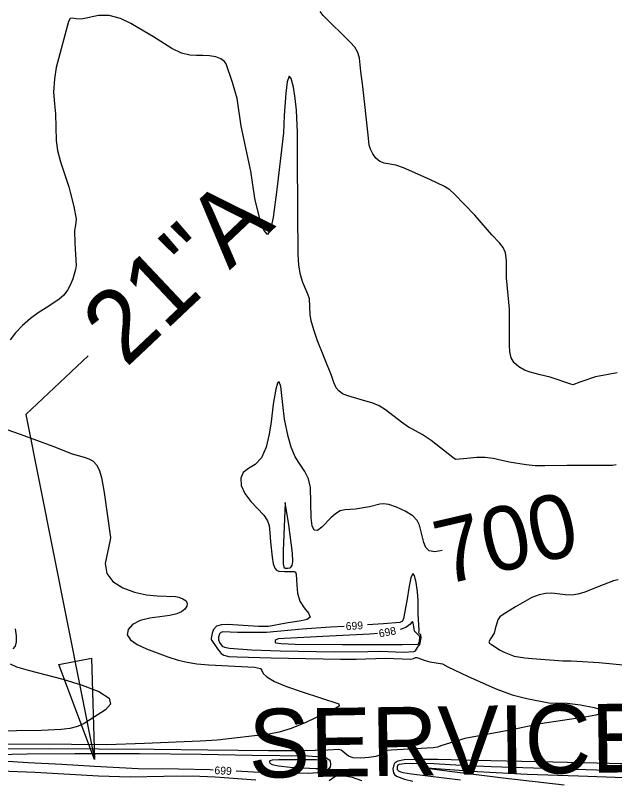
# Model space of a CAD drawing. Extents: x -291892836 to 2945206, y -477993085 to 1832792.
# Drawn here: x 1849872.3 to 1850181.6, y 543914.3 to 544308.6 of the extents above; entities that cross this region are included whole.
import ezdxf

# ---------------------------------------------------------------- set-up
doc = ezdxf.new("R2010")
doc.units = 0
for name, color, linetype in [('DT_X_Contour_Minor', 7, 'Continuous'), ('Level 19', 7, 'Continuous'), ('Level 40', 7, 'Continuous')]:
    doc.layers.add(name, color=color, linetype=linetype)

msp = doc.modelspace()

# ---------------------------------------------------------------- linework, layer by layer
at = {"layer": 'DT_X_Contour_Minor'}
for points in [[(1850180.45, 544076.42), (1850173.94, 544076.29), (1850156.91, 544076.39), (1850145.53, 544076.12), (1850140.58, 544076.25), (1850135.89, 544076.63), (1850127.25, 544078.09), (1850118.95, 544079.96), (1850114.75, 544080.5), (1850110.52, 544080.53), (1850103.63, 544079.8), (1850099.47, 544079.39), (1850098.13, 544080.44), (1850086.86, 544089.2), (1850082.36, 544092.38), (1850076.95, 544095.32), (1850075.23, 544096.11), (1850071.55, 544098.69), (1850063.34, 544105.07), (1850060.09, 544107.07), (1850056.87, 544108.56), (1850050.37, 544110.5), (1850043.86, 544112.24), (1850041.19, 544113.38), (1850039.23, 544114.81), (1850037.93, 544116.37), (1850036.72, 544119.12), (1850035.57, 544122.73), (1850028.23, 544140.77), (1850026.37, 544146.28), (1850025.04, 544150.97), (1850024.44, 544154.35), (1850024.09, 544162.41), (1850023.34, 544164.7), (1850020.68, 544170.73), (1850019.44, 544174.76), (1850018.68, 544179.64), (1850018.32, 544185.39), (1850018.13, 544206.85), (1850018.05, 544236.69), (1850018, 544248.15), (1850017.41, 544259.68), (1850016.77, 544265.63), (1850015.84, 544271.54), (1850014.75, 544275.99), (1850013.66, 544277.25), (1850012.71, 544274.23), (1850011.95, 544268.48), (1850011.17, 544256.94), (1850010.68, 544248.07), (1850007.22, 544218.69), (1850005.38, 544204.25), (1850004.08, 544198.13), (1850002.48, 544195.49), (1850000.63, 544197.72), (1849998.77, 544203.05), (1849996.19, 544213.29), (1849995.21, 544218.91), (1849993.84, 544228.19), (1849988.96, 544251.51), (1849986.88, 544265.7), (1849984.41, 544274), (1849981.22, 544283.63), (1849980.21, 544284.96), (1849978.45, 544286.19), (1849975.77, 544287.14), (1849972.5, 544287.75), (1849969.09, 544287.97), (1849965.82, 544287.86), (1849962.36, 544288), (1849958.18, 544289.11), (1849953.06, 544291.59), (1849943.63, 544297.45), (1849938.67, 544300.51), (1849932.03, 544304.34), (1849926.56, 544306.94), (1849920.71, 544308.59), (1849915.22, 544308.55), (1849906.56, 544306.71), (1849903.76, 544306.76), (1849901.86, 544307.14), (1849900.6, 544306.93), (1849899.74, 544305.42), (1849893.51, 544281.68), (1849892.57, 544275.91), (1849892.04, 544269.02), (1849892.55, 544262.95), (1849893.11, 544257.78), (1849893.37, 544244.02), (1849894.15, 544238.87), (1849895.6, 544233.12), (1849899.95, 544220.13), (1849900.69, 544217.34), (1849902.56, 544209.92), (1849903.69, 544203.37), (1849903.41, 544200.28), (1849902.94, 544197.6), (1849903.12, 544191.01), (1849903.68, 544179.53), (1849903.44, 544177.48), (1849902.08, 544172.74)], [(1850160, 544117.99), (1850148.32, 544121.95), (1850143.13, 544123.22), (1850138.05, 544124.45), (1850135.09, 544125.61), (1850132.18, 544127.24), (1850129.79, 544129.34), (1850128.3, 544131.92), (1850127.57, 544134.95), (1850127.34, 544138.39), (1850127.32, 544156.98), (1850125.89, 544173.14), (1850125.87, 544182.19), (1850125.35, 544186), (1850124.07, 544188.91), (1850122.25, 544191.19), (1850118.25, 544195.45), (1850109.4, 544205.57), (1850098.87, 544216.54), (1850096.5, 544218.55), (1850093.86, 544220.26), (1850086.32, 544223.98), (1850072.7, 544229.92), (1850068.7, 544231.25), (1850062.67, 544232.41), (1850060.39, 544233.27), (1850058.4, 544234.95), (1850056.78, 544237.18), (1850055.62, 544239.52), (1850054.97, 544241.69), (1850054.39, 544246.89), (1850051.65, 544271.96), (1850050.66, 544279.62), (1850049.9, 544286.56), (1850049.05, 544289.51), (1850047.52, 544292.12), (1850045.2, 544294.74), (1850031.18, 544308.5), (1850029.62, 544310.54)], [(1849902.08, 544172.74), (1849900.91, 544169.7), (1849899.34, 544166.74), (1849897.34, 544164.2), (1849894.84, 544161.98), (1849888.2, 544157.69), (1849884.23, 544155.21), (1849880.12, 544152.2), (1849876.1, 544148.59), (1849872.5, 544144.76), (1849869.67, 544141.22)], [(1850182.93, 544124.26), (1850171.71, 544122.17), (1850163.7, 544119.42), (1850160, 544117.99)], [(1850092.56, 544032.47), (1850088.89, 544031.8), (1850085.99, 544032.27), (1850084.14, 544034.1), (1850083.09, 544036.67), (1850080.88, 544045.66), (1850079.78, 544047.92), (1850077.45, 544050.35), (1850073.57, 544052.75), (1850069.04, 544054.81), (1850065.02, 544056.19), (1850062.34, 544056.67), (1850060.4, 544056.43), (1850055.14, 544054.99), (1850047.91, 544053.81), (1850042.31, 544053.57), (1850039.95, 544052.95), (1850037.59, 544051.48), (1850035.21, 544049.36), (1850030.47, 544044.48), (1850028.34, 544042.88), (1850026.65, 544042.95), (1850025.56, 544045.27), (1850024.99, 544049.34), (1850024.62, 544064.94), (1850023.7, 544069.53), (1850021.78, 544073.3), (1850019.26, 544076.82), (1850016.72, 544080.84), (1850014.64, 544085.85), (1850013.07, 544091.28), (1850011.24, 544100.29), (1850010.34, 544107.87), (1850009.3, 544117.14), (1850008.57, 544119.55), (1850007.69, 544118.78), (1850006.79, 544115.74), (1850005.45, 544108.02), (1850004.32, 544098.96), (1850003.31, 544092.55), (1850001.72, 544085.85), (1849999.32, 544080.3), (1849996.07, 544076.91), (1849992.67, 544074.83), (1849989.98, 544072.79), (1849988.71, 544069.78), (1849988.98, 544065.98), (1849990.76, 544061.86), (1849993.84, 544057.83), (1850000.53, 544050.72), (1850002.43, 544047.85), (1850003.32, 544045.44), (1850003.73, 544041.69), (1850003.97, 544037.02), (1850004.83, 544029.12), (1850005.48, 544025.59), (1850006.25, 544023.38), (1850007.19, 544022.28), (1850008.37, 544021.83), (1850011.38, 544021.61), (1850016.27, 544021.66), (1850016.93, 544021.26), (1850017.35, 544020.22), (1850017.63, 544014.69), (1850018.01, 544010.53), (1850019.22, 544006.37), (1850021.44, 544002.85), (1850023.65, 544000.1), (1850024.5, 543998.14), (1850023.03, 543996.95), (1850019.84, 543996.23), (1850012.09, 543994.96), (1850003.08, 543993.32), (1849997.76, 543993.34), (1849982.04, 543994.37), (1849978.74, 543994.21), (1849976.24, 543993.41), (1849974.68, 543991.83), (1849973.87, 543989.92), (1849973.36, 543987.26), (1849973.46, 543986.63), (1849976.73, 543981.82), (1849978.57, 543979.31), (1849980.04, 543978.45), (1849982.48, 543977.91), (1849986.78, 543977.58), (1850004.42, 543977.16), (1850040.13, 543976.38), (1850048.19, 543976.38), (1850063.45, 543976.96), (1850076.2, 543976.42), (1850077.8, 543976.8), (1850079.06, 543977.38), (1850079.52, 543977.33), (1850083.81, 543975.72), (1850086.28, 543975.15), (1850092.74, 543974.06), (1850095.46, 543972.57), (1850105.73, 543967.73), (1850120.01, 543961.35)], [(1849850.55, 544101.04), (1849874.92, 544092.51), (1849891.67, 544086.32), (1849901.73, 544082.37), (1849907.82, 544080.71), (1849910.33, 544079.75), (1849912.48, 544078.56), (1849914.25, 544076.79), (1849915.67, 544074.07), (1849916.8, 544070.23), (1849918.21, 544062.46), (1849921.41, 544039.27), (1849921.35, 544037.94), (1849918.8, 544025.87), (1849919.55, 544020.73), (1849922.73, 544016.47), (1849927.79, 544013.22), (1849933.83, 544010.97), (1849939.97, 544009.67), (1849945.5, 544009.07), (1849954.93, 544008.79), (1849956.8, 544008.35), (1849958.86, 544007.6), (1849960.46, 544006.55), (1849961.09, 544005.23), (1849960.8, 544003.75), (1849959.78, 544002.28), (1849958.14, 544000.93), (1849955.67, 543999.8), (1849952.06, 543998.93), (1849941.85, 543997.58), (1849936.8, 543996.34), (1849932.87, 543994.28), (1849930.51, 543991.67), (1849930.07, 543988.93), (1849931.78, 543986.39), (1849935.26, 543984.03), (1849940, 543981.79), (1849951.11, 543977.63), (1849956.4, 543976), (1849961.05, 543974.84), (1849965.94, 543974.07), (1849972.23, 543973.57), (1849995.72, 543972.36), (1849998.8, 543971.61), (1849999.62, 543970.54), (1850000.18, 543969.11), (1850002.17, 543967.26), (1850006.11, 543965.01), (1850012.23, 543962.41), (1850020.36, 543959.55), (1850039.35, 543953.38), (1850039.46, 543952.26), (1850036.22, 543950.46), (1850022.31, 543943.83), (1850014.72, 543940.68), (1850008.5, 543938.72), (1850003.14, 543937.67), (1849976.53, 543934.72), (1849967.78, 543934.14), (1849938.96, 543932.87), (1849919.53, 543932.22), (1849901.36, 543932.41), (1849865.28, 543932.68)], [(1850182.36, 544076.71), (1850180.45, 544076.42)], [(1850011.67, 544057.33), (1850010.58, 544032.33), (1850010.6, 544025.62), (1850010.99, 544023.84), (1850011.59, 544023.4), (1850012.97, 544023.37), (1850014.04, 544023.6), (1850014.61, 544023.99), (1850015.17, 544024.84), (1850015.5, 544026.92), (1850015.34, 544031.17), (1850013.46, 544045.71), (1850011.67, 544057.33)], [(1850042.11, 543993.36), (1850034.94, 543992.91), (1850020.37, 543991.96), (1850002.05, 543990.24), (1849987.01, 543990.25), (1849979.44, 543990.51), (1849978.37, 543990.16), (1849977.7, 543989.48), (1849977.19, 543987.72), (1849977.16, 543986.36), (1849977.69, 543985.09), (1849979.03, 543983.16), (1849980.23, 543982.62), (1849982.96, 543982.13), (1849994.25, 543981.27), (1850009.03, 543980.72), (1850037.22, 543980.2), (1850054.33, 543980.32), (1850060.77, 543980.51), (1850072.55, 543980.06), (1850078.12, 543980.35), (1850078.82, 543980.8), (1850079.84, 543982.4), (1850080.53, 543983.67), (1850080.91, 543983.75), (1850081.34, 543984.71), (1850081.78, 543987.43), (1850081.65, 543988.98), (1850081.13, 543989.35), (1850080.87, 543989.48), (1850080.55, 543990.14), (1850080.72, 543991.22), (1850080.23, 543999.89), (1850080.22, 544006.69), (1850079.91, 544011.23), (1850079.28, 544015.96), (1850078.39, 544019.61), (1850077.4, 544020.7), (1850076.42, 544018.35), (1850075.57, 544014.06), (1850074.45, 544006.56)], [(1850183.45, 544017.4), (1850181.04, 544016.87), (1850175.73, 544014.85), (1850165.66, 544010.8), (1850162.63, 544009.92), (1850159.51, 544009.54), (1850156.13, 544009.71), (1850149.18, 544010.5), (1850145.93, 544010.39), (1850142.62, 544009.67), (1850138.93, 544008.21), (1850130.41, 544003.48), (1850124.1, 543999.57), (1850122.42, 543998.23), (1850121.37, 543996.66), (1850120.04, 543992.08), (1850119.36, 543989.82), (1850117.57, 543986.9), (1850116.72, 543985.45), (1850117.12, 543984.66), (1850118.08, 543983.95), (1850122.56, 543981.14), (1850124.55, 543980.14), (1850129.74, 543978.08), (1850135.29, 543977.2), (1850138.99, 543976.74), (1850154.88, 543975.59), (1850159.2, 543975.6), (1850173.55, 543974.7), (1850192.96, 543972.77)], [(1850074.45, 544006.56), (1850072.66, 543997.46), (1850072.14, 543996.09), (1850070.82, 543995.44), (1850062.29, 543994.64), (1850054.09, 543994.12)], [(1850006.47, 543985.33), (1850006.51, 543985.08), (1850006.86, 543984.89), (1850009.55, 543984.52), (1850016.78, 543984.15), (1850041.26, 543984.03), (1850072.02, 543983.94), (1850080.21, 543984.12), (1850080.91, 543985.41), (1850081.08, 543988.18), (1850080.87, 543988.33), (1850078.41, 543990.95), (1850078.2, 543992.19), (1850077.72, 543995.05), (1850077.37, 543995.84), (1850076.91, 543995.46), (1850075.92, 543994.28), (1850073.89, 543992.85), (1850070.99, 543991.81)], [(1849872.2, 543992.09), (1849872.73, 543988.56), (1849872.87, 543985.44), (1849872.37, 543983.12), (1849871.11, 543981.82)], [(1850059.17, 543989.75), (1850055.22, 543989.36), (1850031.01, 543988.14), (1850007.95, 543986.9), (1850006.91, 543986.5), (1850006.52, 543986.03), (1850006.47, 543985.33)], [(1849869.66, 543974.03), (1849872.92, 543972.5), (1849878.94, 543970.72), (1849896.81, 543966.06), (1849906.84, 543963.01), (1849915.5, 543959.69), (1849920.82, 543956.36), (1849921.52, 543953.25), (1849918.9, 543950.38), (1849907.95, 543943.31), (1849904.44, 543941.75), (1849900.47, 543940.75)], [(1850120.01, 543961.35), (1850128.68, 543958), (1850136.28, 543956.16), (1850147.57, 543954), (1850157.03, 543953.71), (1850163.91, 543952.81), (1850171, 543951.52), (1850175.56, 543950.12), (1850175.58, 543948.79), (1850171.92, 543947.6), (1850166.19, 543946.54), (1850143.11, 543943.09), (1850128.6, 543940.05), (1850104.3, 543935.55), (1850092.46, 543931.85), (1850090.13, 543931.09), (1850087.94, 543930.67), (1850078.67, 543930.17), (1850066.34, 543929.58), (1850063.08, 543929.16), (1850061.76, 543928.66), (1850061.23, 543927.52), (1850060.43, 543926.91), (1850058.42, 543926.28), (1850054.84, 543925.67), (1850050.56, 543925.33), (1850046.76, 543925.54), (1850044.29, 543926.46), (1850040.49, 543929.55), (1850039.07, 543929.78), (1850033.78, 543929.57), (1850020.31, 543929.1), (1850002.99, 543929.07), (1849971.67, 543929.49), (1849943.98, 543929.85), (1849915.31, 543930.01), (1849889.84, 543930.14), (1849860.17, 543930)], [(1849900.47, 543940.75), (1849896.04, 543940.19), (1849885.88, 543939.71), (1849859.88, 543939.24), (1849828.67, 543938.76), (1849808.91, 543938.36), (1849782.93, 543937.37), (1849757.88, 543936.39), (1849725.6, 543936.08), (1849702.78, 543936.2), (1849668.27, 543936.61), (1849636.03, 543936.9), (1849604.25, 543937.36), (1849577.59, 543937.82), (1849552.39, 543938.39), (1849525.25, 543939.05), (1849499.13, 543939.58)], [(1849862.81, 543927.21), (1849878.47, 543927.62), (1849903, 543927.77), (1849936.41, 543927.8), (1849968.21, 543927.43), (1849994.62, 543926.97), (1850023.32, 543926.56), (1850027.98, 543926.31), (1850031.18, 543925.89), (1850033.15, 543925.31), (1850034.26, 543924.58), (1850034.82, 543923.75), (1850035.06, 543922.11), (1850034.83, 543920.82), (1850034.29, 543920.1), (1850033.22, 543919.21), (1850031.32, 543918.34), (1850028.27, 543917.73), (1850023.87, 543917.54), (1849995.22, 543918.11), (1849986.38, 543918.58)], [(1849896.39, 543922.18), (1849878.91, 543922.98), (1849862.93, 543923.98)], [(1849974.4, 543919.21), (1849972.85, 543919.29), (1849956.56, 543919.64), (1849935.71, 543919.9), (1849913.29, 543921.11), (1849896.39, 543922.18)], [(1850033.15, 543920.41), (1850033.04, 543924.06), (1850032.63, 543924.24), (1850027.52, 543924.51), (1850008.27, 543924.55), (1850004.91, 543924.35), (1850003.67, 543924.01), (1850003.48, 543923.51), (1850003.64, 543922.85), (1850004.86, 543922.12), (1850008.2, 543921.39), (1850014.21, 543920.75), (1850027.47, 543919.99), (1850032.56, 543920.1), (1850033.15, 543920.41)], [(1850191.91, 543922.33), (1850172.24, 543922.81), (1850149.71, 543923.35), (1850117.71, 543923.97), (1850090.46, 543924.71), (1850078.52, 543924.7), (1850073.03, 543924.43), (1850069.71, 543923.85), (1850068.16, 543923.01), (1850067.6, 543922), (1850067.22, 543919.78), (1850067.43, 543917.74), (1850067.98, 543916.86), (1850069.11, 543916.03)], [(1850088.37, 543922.44), (1850074.42, 543922.56), (1850070.44, 543922.19), (1850069.76, 543921.81), (1850069.39, 543920.88), (1850069.43, 543919.47), (1850070.18, 543918.71), (1850072.4, 543918), (1850076.86, 543917.29), (1850102.13, 543914.25)], [(1850195.43, 543918.58), (1850172.41, 543919.22), (1850145.09, 543920.01), (1850118.07, 543920.87), (1850102.44, 543921.59), (1850088.37, 543922.44)], [(1849841.44, 543919.56), (1849851.32, 543919.4), (1849882.62, 543918.15), (1849915.23, 543916.34), (1849931.58, 543915.78), (1849948.94, 543916.07), (1849963.53, 543916.3), (1849975.5, 543915.77), (1849996.44, 543914.12)], [(1850531.16, 543921.85), (1850502.09, 543919.94), (1850490.63, 543919.25), (1850463.84, 543918.67), (1850437.32, 543917.91), (1850414.55, 543916.77), (1850386.45, 543915.05), (1850377.38, 543914.54), (1850363.53, 543914.37), (1850340.21, 543915), (1850317.95, 543915.11), (1850289.18, 543915.13), (1850261.34, 543915.14), (1850233.92, 543915.26), (1850208.47, 543914.96), (1850186.72, 543915.18), (1850162.88, 543916.04), (1850136.49, 543917), (1850110.93, 543918.25), (1850084.67, 543920.14), (1850097.74, 543918.5), (1850124.02, 543915.27), (1850155.55, 543911.67)], [(1850034.37, 543913.92), (1850037.19, 543915.96), (1850039.4, 543916.52), (1850042.6, 543916.29), (1850046.13, 543915.52), (1850050.94, 543913.8)], [(1850069.11, 543916.03), (1850073.22, 543914.51), (1850077.46, 543913.56)]]:
    msp.add_lwpolyline(points, dxfattribs=at)
at = {"layer": 'Level 40'}
for p, q in [((1849877.83, 544102.74), (1849909.9, 544133.01)), ((1849877.83, 544102.74), (1849913.24, 543924.75)), ((1849894.77, 543973.66), (1849911.61, 543977.01)), ((1849913.24, 543924.75), (1849894.77, 543973.66)), ((1849911.61, 543977.01), (1849913.24, 543924.75))]:
    msp.add_line(p, q, dxfattribs=at)

# ---------------------------------------------------------------- texts
at = {"layer": 'Level 19'}
for s, height, rotation, p in [('700', 33, 13.0405, (1850093.18, 544014.64)), ('699', 4, 3.6096, (1850042.98, 543991.41)), ('698', 4, 10.9664, (1850060.35, 543987.63)), ('699', 4, 356.9814, (1849975.03, 543917.17))]:
    msp.add_text(s, height=height, rotation=rotation, dxfattribs=at).set_placement(p)
at = {"layer": 'Level 40'}
for s, height, rotation, p in [('21"A', 37.5, 43.3446, (1849929.4, 544126.42)), ('SERVICE RD. #5', 35.5, 0.8435, (1849992.93, 543915.18))]:
    msp.add_text(s, height=height, rotation=rotation, dxfattribs=at).set_placement(p)

doc.saveas('drawing.dxf')
